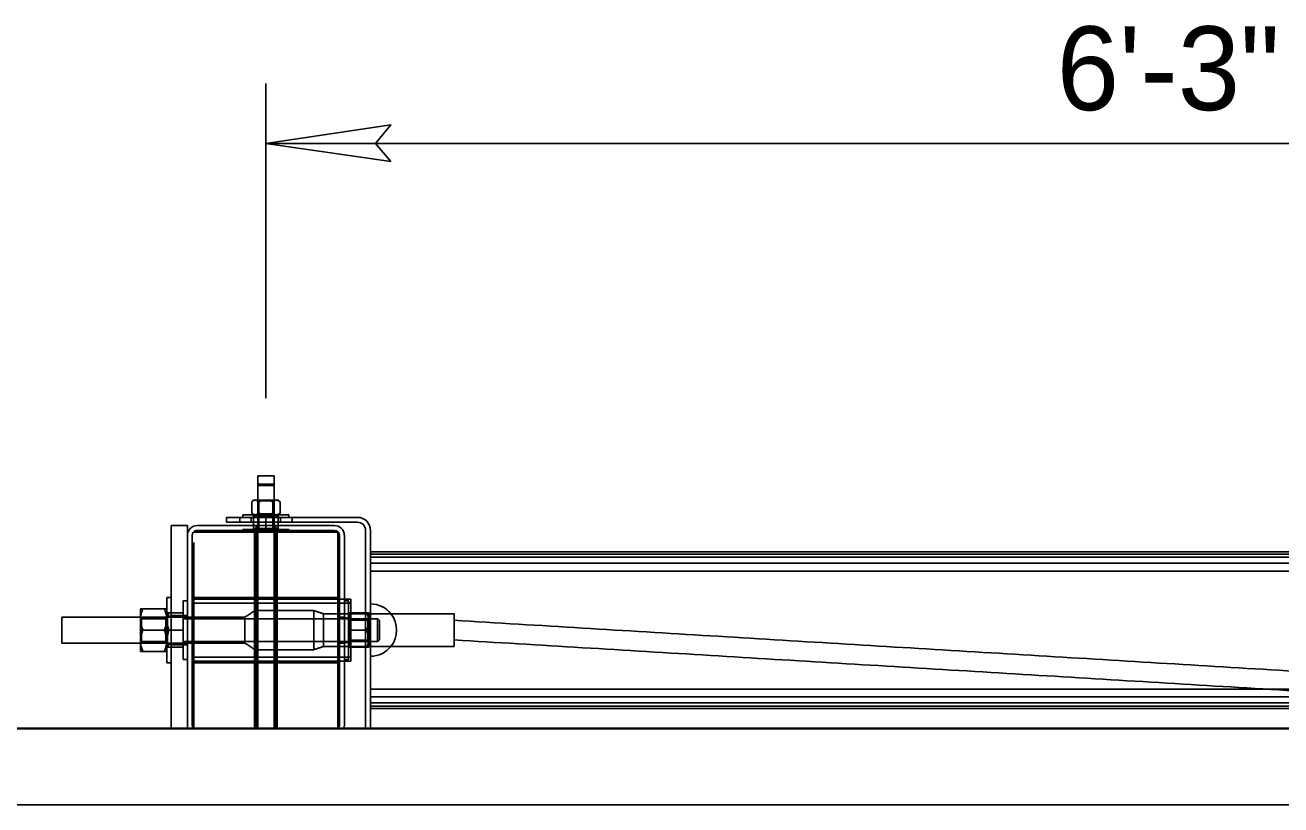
# Model space of a CAD drawing. Extents: x 12.2 to 54.5, y -7.8 to 16.1.
# Drawn here: x 13.517 to 14.416, y 11.987 to 12.545 of the extents above; entities that cross this region are included whole.
import ezdxf

# ---------------------------------------------------------------- set-up
doc = ezdxf.new("R2010")
doc.units = 0
for name, color, linetype in [('BORD-LINE', 7, 'Continuous'), ('DETL-DIMS', 7, 'Continuous'), ('DETL-NOTE', 7, 'Continuous')]:
    doc.layers.add(name, color=color, linetype=linetype)

msp = doc.modelspace()

# ---------------------------------------------------------------- linework, layer by layer
at = {"layer": 'BORD-LINE'}
for p, q in [((13.68348, 12.22238), (13.69519, 12.22238)), ((13.68348, 12.21561), (13.69519, 12.21561)), ((13.68449, 12.21663), (13.69417, 12.21663)), ((13.67919, 12.19579), (13.67919, 12.20392)), ((13.68173, 12.20509), (13.68055, 12.20509)), ((13.68348, 12.20509), (13.68173, 12.20509)), ((13.68933, 12.20509), (13.68348, 12.20509)), ((13.68426, 12.19579), (13.68426, 12.20392)), ((13.68436, 12.20447), (13.69431, 12.20447)), ((13.69519, 12.20509), (13.68933, 12.20509)), ((13.69441, 12.19579), (13.69441, 12.20392)), ((13.69694, 12.20509), (13.69519, 12.20509)), ((13.69812, 12.20509), (13.69694, 12.20509)), ((13.69948, 12.19579), (13.69948, 12.20392)), ((13.68055, 12.19274), (13.66124, 12.19274)), ((13.66124, 12.19274), (13.66124, 12.18923)), ((13.68348, 12.19462), (13.67294, 12.19462)), ((13.6788, 12.19274), (13.6788, 12.18923)), ((13.68494, 12.19455), (13.68055, 12.19455)), ((13.68055, 12.18525), (13.68055, 12.19338)), ((13.69812, 12.19274), (13.68055, 12.19274)), ((13.69519, 12.19464), (13.68348, 12.19464)), ((13.69519, 12.19462), (13.68348, 12.19462)), ((13.68933, 12.19525), (13.68436, 12.19525)), ((13.68436, 12.19394), (13.69431, 12.19394)), ((13.69373, 12.19455), (13.68494, 12.19455)), ((13.69431, 12.19525), (13.68933, 12.19525)), ((13.68933, 12.18525), (13.68933, 12.19338)), ((13.69812, 12.19455), (13.69373, 12.19455)), ((13.70572, 12.19462), (13.69519, 12.19462)), ((13.69812, 12.18525), (13.69812, 12.19338)), ((13.75489, 12.19274), (13.69812, 12.19274)), ((13.69987, 12.19274), (13.69987, 12.18923)), ((13.63314, 12.18689), (13.62143, 12.18689)), ((13.62143, 12.04185), (13.62143, 12.18689)), ((13.63314, 12.04185), (13.63314, 12.18689)), ((13.64016, 12.18689), (13.68055, 12.18689)), ((13.64016, 12.18338), (13.67294, 12.18338)), ((13.66124, 12.18923), (13.68055, 12.18923)), ((13.70572, 12.18408), (13.67294, 12.18408)), ((13.67294, 12.18338), (13.70572, 12.18338)), ((13.68055, 12.18923), (13.69812, 12.18923)), ((13.68055, 12.18689), (13.69812, 12.18689)), ((13.69519, 12.1841), (13.68348, 12.1841)), ((13.69431, 12.18471), (13.68436, 12.18471)), ((13.69812, 12.18923), (13.75489, 12.18923)), ((13.69812, 12.18689), (13.7385, 12.18689)), ((13.70572, 12.18338), (13.7385, 12.18338)), ((13.76075, 12.18338), (13.76075, 12.12367)), ((13.76426, 12.12367), (13.76426, 12.18338)), ((13.63665, 12.12133), (13.63665, 12.17987)), ((13.63782, 12.18221), (13.74084, 12.18221)), ((13.63782, 12.04172), (13.63782, 12.17483)), ((13.74084, 12.18221), (13.74084, 12.04172)), ((13.74201, 12.17987), (13.74201, 12.13421)), ((13.74553, 12.17987), (13.74553, 12.13421)), ((15.01924, 12.16816), (13.76426, 12.16816)), ((13.76426, 12.1307), (13.76426, 12.16816)), ((15.01924, 12.16632), (13.76426, 12.16632)), ((15.01924, 12.16411), (13.76426, 12.16411)), ((15.01924, 12.15983), (13.76426, 12.15983)), ((15.01924, 12.15429), (13.76426, 12.15429)), ((13.61844, 12.08855), (13.61844, 12.13538)), ((13.63014, 12.13304), (13.63014, 12.11197)), ((13.74201, 12.13421), (13.74201, 12.08972)), ((13.74553, 12.13421), (13.74553, 12.08972)), ((13.74852, 12.09089), (13.74852, 12.13304)), ((13.75021, 12.13421), (13.75021, 12.08972)), ((13.54329, 12.1026), (13.54329, 12.12133)), ((13.59948, 12.12719), (13.59948, 12.11958)), ((13.5995, 12.1026), (13.5995, 12.12133)), ((13.60032, 12.10377), (13.60032, 12.12016)), ((13.60135, 12.12719), (13.61656, 12.12719)), ((13.61762, 12.12016), (13.61762, 12.10377)), ((13.61883, 12.11811), (13.61883, 12.12425)), ((13.63014, 12.12425), (13.61993, 12.12425)), ((13.63665, 12.1026), (13.63665, 12.12133)), ((13.6744, 12.1026), (13.6744, 12.12133)), ((13.68143, 12.09792), (13.68143, 12.12601)), ((13.7306, 12.10026), (13.7306, 12.12367)), ((13.74854, 12.10377), (13.74854, 12.12016)), ((13.75016, 12.12425), (13.76142, 12.12425)), ((13.76075, 12.12367), (13.76075, 12.10026)), ((13.76306, 12.11811), (13.76306, 12.12425)), ((13.76426, 12.10026), (13.76426, 12.12367)), ((13.76939, 12.12016), (13.76939, 12.10377)), ((13.82425, 12.10026), (13.82425, 12.12367)), ((13.59948, 12.11958), (13.59948, 12.10436)), ((13.60135, 12.11197), (13.61656, 12.11197)), ((13.61883, 12.10582), (13.61883, 12.11811)), ((13.63014, 12.11197), (13.61993, 12.11197)), ((13.63014, 12.11197), (13.63014, 12.09089)), ((13.74926, 12.1048), (13.74926, 12.11914)), ((13.75016, 12.11197), (13.76142, 12.11197)), ((13.76234, 12.11914), (13.76234, 12.1048)), ((13.76306, 12.10582), (13.76306, 12.11811)), ((13.77063, 12.11892), (13.77063, 12.10501)), ((13.59948, 12.09675), (13.59948, 12.10436)), ((13.61883, 12.09968), (13.61883, 12.10582)), ((13.63665, 12.04407), (13.63665, 12.1026)), ((13.76306, 12.09968), (13.76306, 12.10582)), ((13.60135, 12.09675), (13.61656, 12.09675)), ((13.63014, 12.09968), (13.61993, 12.09968)), ((13.75016, 12.09968), (13.76142, 12.09968)), ((13.76075, 12.10026), (13.76075, 12.04185)), ((13.76426, 12.04185), (13.76426, 12.10026)), ((13.76426, 12.05577), (13.76426, 12.09323)), ((13.74201, 12.08972), (13.74201, 12.04407)), ((13.74553, 12.08972), (13.74553, 12.04407)), ((15.01924, 12.06964), (13.76426, 12.06964)), ((15.01924, 12.0641), (13.76426, 12.0641)), ((15.01924, 12.05983), (13.76426, 12.05983)), ((15.01924, 12.05761), (13.76426, 12.05761)), ((14.55799, 12.05577), (13.76426, 12.05577)), ((13.63782, 12.04185), (12.85346, 12.04185)), ((16.74348, 12.04118), (12.85346, 12.0414)), ((13.74084, 12.04185), (13.63782, 12.04185)), ((13.74084, 12.04172), (13.63782, 12.04172)), ((15.04266, 12.04185), (13.74084, 12.04185)), ((14.85769, 12.04172), (13.74084, 12.04172)), ((16.73075, 11.98677), (12.76364, 11.98677))]:
    msp.add_line(p, q, dxfattribs=at)
for points in [[(13.6335, 12.04185), (13.63328, 12.0427), (13.63314, 12.04407)], [(13.74553, 12.04407), (13.74539, 12.0427), (13.74517, 12.04185)]]:
    msp.add_lwpolyline(points, dxfattribs=at)
for centre, radius, start, end in [((13.75489, 12.18338), 0.00937, 0.0035, 89.99686), ((13.64016, 12.17987), 0.00702, 89.995, 180.00319), ((13.64016, 12.17987), 0.00351, 89.98517, 180.01299), ((13.7385, 12.17987), 0.00702, 359.99681, 90.005), ((13.7385, 12.17987), 0.00351, 0.00659, 89.99525), ((13.75489, 12.18338), 0.00585, 0.0027, 89.99679), ((13.76426, 12.11197), 0.01873, 38.68364, 89.99845), ((13.76426, 12.11197), 0.01873, 321.3166, 38.6834), ((13.76426, 12.11197), 0.01873, 270.00156, 321.31631), ((13.64016, 12.04407), 0.00351, 179.99758, 219.01778), ((13.7385, 12.04407), 0.00351, 320.98222, 0.00242)]:
    msp.add_arc(centre, radius, start, end, dxfattribs=at)
for points, degree in [([(13.68348, 12.19455), (13.68348, 12.22238)], 1), ([(13.69519, 12.22238), (13.69519, 12.19455)], 1), ([(13.68348, 12.21561), (13.68449, 12.21663)], 1), ([(13.69417, 12.21663), (13.69519, 12.21561)], 1), ([(13.67919, 12.20392), (13.68055, 12.20509)], 1), ([(13.67919, 12.20392), (13.67957, 12.20422), (13.6803, 12.2048), (13.68125, 12.20509), (13.68171, 12.20509), (13.68173, 12.20509)], 3), ([(13.68173, 12.20509), (13.68157, 12.20506)], 1), ([(13.68173, 12.20509), (13.68209, 12.20505), (13.68273, 12.20498), (13.68325, 12.20462), (13.68348, 12.20447)], 3), ([(13.68436, 12.20447), (13.68348, 12.20509)], 1), ([(13.68348, 12.20447), (13.6836, 12.2044), (13.68389, 12.20425), (13.68413, 12.20404), (13.68426, 12.20392)], 3), ([(13.68426, 12.20392), (13.68469, 12.20409), (13.68571, 12.2045), (13.6874, 12.20498), (13.68868, 12.20505), (13.68933, 12.20509)], 3), ([(13.68436, 12.19525), (13.68436, 12.20447)], 1), ([(13.68933, 12.20509), (13.68945, 12.20509), (13.69021, 12.20508), (13.69163, 12.20489), (13.6932, 12.20442), (13.69411, 12.20404), (13.69441, 12.20392)], 3), ([(13.69519, 12.20509), (13.69431, 12.20447)], 1), ([(13.69431, 12.20447), (13.69431, 12.19525)], 1), ([(13.69441, 12.20392), (13.69519, 12.20446)], 1), ([(13.69519, 12.20446), (13.69532, 12.20456), (13.69582, 12.20493), (13.69647, 12.20509), (13.69693, 12.20509), (13.69694, 12.20509)], 3), ([(13.69694, 12.20509), (13.6973, 12.20504), (13.69807, 12.20494), (13.69889, 12.2044), (13.69934, 12.20403), (13.69948, 12.20392)], 3), ([(13.69812, 12.20509), (13.69948, 12.20392)], 1), ([(13.6706, 12.18923), (13.6706, 12.19274)], 1), ([(13.67294, 12.19274), (13.67294, 12.19462)], 1), ([(13.68055, 12.19462), (13.67919, 12.19579)], 1), ([(13.67919, 12.19579), (13.67957, 12.19548), (13.6803, 12.1949), (13.68125, 12.19462), (13.68171, 12.19462), (13.68173, 12.19462)], 3), ([(13.68055, 12.19338), (13.68123, 12.19369), (13.6826, 12.19431), (13.68414, 12.19455), (13.68492, 12.19455), (13.68494, 12.19455)], 3), ([(13.68055, 12.19338), (13.68055, 12.19355), (13.68055, 12.19388), (13.68055, 12.19427), (13.68055, 12.19449), (13.68055, 12.19455)], 3), ([(13.68173, 12.19462), (13.68157, 12.19465)], 1), ([(13.68173, 12.19462), (13.68209, 12.19466), (13.68273, 12.19473), (13.68325, 12.19509), (13.68348, 12.19524)], 3), ([(13.68319, 12.19274), (13.68319, 12.19462)], 1), ([(13.68348, 12.19524), (13.6836, 12.19531), (13.68389, 12.19546), (13.68413, 12.19567), (13.68426, 12.19579)], 3), ([(13.68348, 12.19464), (13.68436, 12.19525)], 1), ([(13.68436, 12.19394), (13.68348, 12.19455)], 1), ([(13.68348, 12.04138), (13.68348, 12.19455)], 1), ([(13.68426, 12.19579), (13.68469, 12.19561), (13.68571, 12.1952), (13.6874, 12.19473), (13.68868, 12.19465), (13.68933, 12.19462)], 3), ([(13.68436, 12.18471), (13.68436, 12.19394)], 1), ([(13.68494, 12.19455), (13.68556, 12.19451), (13.68682, 12.19441), (13.68827, 12.19389), (13.68909, 12.1935), (13.68933, 12.19338)], 3), ([(13.68933, 12.19462), (13.68945, 12.19462), (13.69021, 12.19463), (13.69163, 12.19482), (13.6932, 12.19529), (13.69411, 12.19566), (13.69441, 12.19579)], 3), ([(13.68933, 12.19338), (13.69001, 12.19369), (13.69139, 12.19431), (13.69293, 12.19455), (13.69371, 12.19455), (13.69373, 12.19455)], 3), ([(13.69373, 12.19455), (13.69434, 12.19451), (13.6956, 12.19441), (13.69706, 12.19389), (13.69788, 12.1935), (13.69812, 12.19338)], 3), ([(13.69431, 12.19525), (13.69519, 12.19464)], 1), ([(13.69519, 12.19455), (13.69431, 12.19394)], 1), ([(13.69431, 12.19394), (13.69431, 12.18471)], 1), ([(13.69441, 12.19579), (13.69519, 12.19525)], 1), ([(13.69519, 12.19525), (13.69532, 12.19515), (13.69582, 12.19478), (13.69647, 12.19462), (13.69693, 12.19462), (13.69694, 12.19462)], 3), ([(13.69519, 12.19455), (13.69519, 12.04138)], 1), ([(13.69548, 12.19462), (13.69548, 12.19274)], 1), ([(13.69694, 12.19462), (13.6973, 12.19467), (13.69807, 12.19477), (13.69889, 12.1953), (13.69934, 12.19567), (13.69948, 12.19579)], 3), ([(13.69948, 12.19579), (13.69812, 12.19462)], 1), ([(13.69812, 12.19338), (13.69812, 12.19355), (13.69812, 12.19388), (13.69812, 12.19427), (13.69812, 12.19449), (13.69812, 12.19455)], 3), ([(13.70572, 12.19462), (13.70572, 12.19274)], 1), ([(13.70806, 12.19274), (13.70806, 12.18923)], 1), ([(13.67294, 12.18221), (13.67294, 12.18408)], 1), ([(13.68055, 12.18525), (13.68123, 12.18494), (13.6826, 12.18432), (13.68414, 12.18408), (13.68492, 12.18408), (13.68494, 12.18408)], 3), ([(13.68055, 12.18525), (13.68055, 12.18508), (13.68055, 12.18475), (13.68055, 12.18436), (13.68055, 12.18414), (13.68055, 12.18408)], 3), ([(13.68231, 12.18338), (13.68231, 12.18689)], 1), ([(13.68319, 12.18221), (13.68319, 12.18408)], 1), ([(13.68348, 12.1841), (13.68436, 12.18471)], 1), ([(13.68348, 12.18408), (13.68348, 12.1841)], 1), ([(13.68494, 12.18408), (13.68556, 12.18413), (13.68682, 12.18422), (13.68827, 12.18474), (13.68909, 12.18514), (13.68933, 12.18525)], 3), ([(13.68933, 12.18525), (13.69001, 12.18494), (13.69139, 12.18432), (13.69293, 12.18408), (13.69371, 12.18408), (13.69373, 12.18408)], 3), ([(13.69373, 12.18408), (13.69434, 12.18413), (13.6956, 12.18422), (13.69706, 12.18475), (13.69788, 12.18514), (13.69812, 12.18525)], 3), ([(13.69431, 12.18471), (13.69519, 12.1841)], 1), ([(13.69519, 12.1841), (13.69519, 12.18408)], 1), ([(13.69548, 12.18408), (13.69548, 12.18221)], 1), ([(13.69636, 12.18689), (13.69636, 12.18338)], 1), ([(13.69812, 12.18525), (13.69812, 12.18508), (13.69812, 12.18475), (13.69812, 12.18436), (13.69812, 12.18414), (13.69812, 12.18408)], 3), ([(13.70572, 12.18408), (13.70572, 12.18221)], 1), ([(13.68114, 12.04172), (13.68114, 12.18221)], 1), ([(13.68231, 12.04172), (13.68231, 12.18221)], 1), ([(13.69636, 12.18221), (13.69636, 12.04172)], 1), ([(13.69753, 12.18221), (13.69753, 12.04172)], 1), ([(13.61844, 12.13538), (13.62143, 12.13538)], 1), ([(13.63014, 12.13304), (13.63314, 12.13304)], 1), ([(13.63782, 12.13538), (13.74084, 12.13538)], 1), ([(13.63782, 12.13421), (13.74084, 12.13421)], 1), ([(13.63782, 12.13132), (13.75021, 12.13132)], 1), ([(13.74084, 12.13421), (13.75021, 12.13421)], 1), ([(13.74553, 12.13304), (13.74852, 12.13304)], 1), ([(13.54329, 12.12133), (13.59948, 12.12133)], 1), ([(13.60135, 12.12719), (13.60091, 12.12612), (13.60001, 12.12398), (13.59952, 12.12137), (13.59949, 12.11989), (13.59948, 12.11958)], 3), ([(13.59948, 12.12719), (13.59949, 12.12719), (13.59968, 12.12719), (13.60022, 12.12719), (13.60084, 12.12719), (13.60127, 12.12719), (13.60135, 12.12719)], 3), ([(13.59948, 12.12133), (13.63314, 12.12133)], 1), ([(13.59948, 12.12133), (13.5995, 12.12133)], 1), ([(13.5995, 12.12133), (13.60032, 12.12016)], 1), ([(13.60032, 12.12016), (13.61762, 12.12016)], 1), ([(13.61656, 12.12719), (13.61701, 12.12612), (13.6179, 12.12398), (13.6184, 12.12137), (13.61843, 12.11989), (13.61844, 12.11958)], 3), ([(13.61844, 12.12719), (13.61842, 12.12719), (13.61824, 12.12719), (13.61769, 12.12719), (13.61708, 12.12719), (13.61664, 12.12719), (13.61656, 12.12719)], 3), ([(13.61762, 12.12016), (13.61844, 12.12133)], 1), ([(13.61844, 12.12191), (13.62143, 12.12191)], 1), ([(13.61993, 12.12425), (13.61962, 12.12326), (13.619, 12.12125), (13.61889, 12.11916), (13.61883, 12.11811)], 3), ([(13.61883, 12.12425), (13.61889, 12.12425), (13.61912, 12.12425), (13.61949, 12.12425), (13.61979, 12.12425), (13.61993, 12.12425)], 3), ([(13.62143, 12.1225), (13.63314, 12.1225)], 1), ([(13.63014, 12.12075), (13.63314, 12.12075)], 1), ([(13.63014, 12.12016), (13.76939, 12.12016)], 1), ([(13.63314, 12.12133), (13.63782, 12.12133)], 1), ([(13.63782, 12.12133), (13.6744, 12.12133)], 1), ([(13.6744, 12.12133), (13.67532, 12.12188), (13.67705, 12.1229), (13.67937, 12.12451), (13.68078, 12.12554), (13.68143, 12.12601)], 3), ([(13.68143, 12.12601), (13.72357, 12.12601)], 1), ([(13.72357, 12.09792), (13.72357, 12.09801), (13.72357, 12.09836), (13.72357, 12.09915), (13.72357, 12.10043), (13.72357, 12.10216), (13.72357, 12.10426), (13.72357, 12.10666), (13.72357, 12.10926), (13.72357, 12.11197), (13.72357, 12.11467), (13.72357, 12.11727), (13.72357, 12.11967), (13.72357, 12.12177), (13.72357, 12.1235), (13.72357, 12.12478), (13.72357, 12.12557), (13.72357, 12.12592), (13.72357, 12.12601)], 3), ([(13.72357, 12.12601), (13.7306, 12.12367)], 1), ([(13.7306, 12.12367), (13.75021, 12.12367)], 1), ([(13.74201, 12.12133), (13.74553, 12.12133)], 1), ([(13.74553, 12.12075), (13.74852, 12.12075)], 1), ([(13.75016, 12.12425), (13.74973, 12.1233), (13.74886, 12.12138), (13.74853, 12.11923), (13.74852, 12.11814), (13.74852, 12.11811)], 3), ([(13.75016, 12.12425), (13.74993, 12.12425), (13.74947, 12.12425), (13.74892, 12.12425), (13.74861, 12.12425), (13.74852, 12.12425)], 3), ([(13.74852, 12.12016), (13.74854, 12.12016)], 1), ([(13.74854, 12.12016), (13.74926, 12.11914)], 1), ([(13.75021, 12.12367), (13.82425, 12.12367)], 1), ([(13.76142, 12.12425), (13.76185, 12.1233), (13.76272, 12.12138), (13.76306, 12.11923), (13.76306, 12.11814), (13.76306, 12.11811)], 3), ([(13.76142, 12.12425), (13.76165, 12.12425), (13.76212, 12.12425), (13.76266, 12.12425), (13.76297, 12.12425), (13.76306, 12.12425)], 3), ([(13.76234, 12.11914), (13.76306, 12.12016)], 1), ([(13.76939, 12.12016), (13.77063, 12.11892)], 1), ([(13.59948, 12.11958), (13.59954, 12.11858), (13.59967, 12.11656), (13.60046, 12.11403), (13.60111, 12.11253), (13.60135, 12.11197)], 3), ([(13.60135, 12.11197), (13.60091, 12.1109), (13.60001, 12.10876), (13.59952, 12.10615), (13.59949, 12.10467), (13.59948, 12.10436)], 3), ([(13.61844, 12.11958), (13.61837, 12.11858), (13.61825, 12.11656), (13.61746, 12.11403), (13.61681, 12.11253), (13.61656, 12.11197)], 3), ([(13.61656, 12.11197), (13.61701, 12.1109), (13.6179, 12.10876), (13.6184, 12.10615), (13.61843, 12.10467), (13.61844, 12.10436)], 3), ([(13.61883, 12.11811), (13.61883, 12.11796), (13.61884, 12.11686), (13.61908, 12.11477), (13.61964, 12.11291), (13.61993, 12.11197)], 3), ([(13.61993, 12.11197), (13.61962, 12.11097), (13.619, 12.10897), (13.61889, 12.10687), (13.61883, 12.10582)], 3), ([(13.74852, 12.11811), (13.74859, 12.11725), (13.74872, 12.11549), (13.74945, 12.11345), (13.75, 12.1123), (13.75016, 12.11197)], 3), ([(13.75016, 12.11197), (13.74973, 12.11101), (13.74886, 12.10909), (13.74853, 12.10694), (13.74852, 12.10585), (13.74852, 12.10582)], 3), ([(13.74926, 12.11914), (13.76234, 12.11914)], 1), ([(13.76306, 12.11811), (13.763, 12.11725), (13.76287, 12.11549), (13.76213, 12.11345), (13.76158, 12.1123), (13.76142, 12.11197)], 3), ([(13.76142, 12.11197), (13.76185, 12.11101), (13.76272, 12.10909), (13.76306, 12.10694), (13.76306, 12.10585), (13.76306, 12.10582)], 3), ([(13.82425, 12.11899), (14.55799, 12.0745)], 1), ([(13.59948, 12.1026), (13.54329, 12.1026)], 1), ([(13.59948, 12.10436), (13.59954, 12.10336), (13.59967, 12.10134), (13.60046, 12.09881), (13.60111, 12.09731), (13.60135, 12.09675)], 3), ([(13.63314, 12.1026), (13.59948, 12.1026)], 1), ([(13.5995, 12.1026), (13.59948, 12.1026)], 1), ([(13.60032, 12.10377), (13.5995, 12.1026)], 1), ([(13.61762, 12.10377), (13.60032, 12.10377)], 1), ([(13.61844, 12.10436), (13.61837, 12.10336), (13.61825, 12.10134), (13.61746, 12.09881), (13.61681, 12.09731), (13.61656, 12.09675)], 3), ([(13.61844, 12.1026), (13.61762, 12.10377)], 1), ([(13.61883, 12.10582), (13.61883, 12.10568), (13.61884, 12.10457), (13.61908, 12.10248), (13.61964, 12.10062), (13.61993, 12.09968)], 3), ([(13.76939, 12.10377), (13.63014, 12.10377)], 1), ([(13.63314, 12.10318), (13.63014, 12.10318)], 1), ([(13.63782, 12.1026), (13.63314, 12.1026)], 1), ([(13.6744, 12.1026), (13.63782, 12.1026)], 1), ([(13.68143, 12.09792), (13.68078, 12.09839), (13.67937, 12.09942), (13.67705, 12.10103), (13.67532, 12.10206), (13.6744, 12.1026)], 3), ([(13.74553, 12.1026), (13.74201, 12.1026)], 1), ([(13.74852, 12.10318), (13.74553, 12.10318)], 1), ([(13.74852, 12.10582), (13.74859, 12.10496), (13.74872, 12.1032), (13.74945, 12.10117), (13.75, 12.10002), (13.75016, 12.09968)], 3), ([(13.74854, 12.10377), (13.74852, 12.10377)], 1), ([(13.74926, 12.1048), (13.74854, 12.10377)], 1), ([(13.76234, 12.1048), (13.74926, 12.1048)], 1), ([(13.76306, 12.10582), (13.763, 12.10496), (13.76287, 12.1032), (13.76213, 12.10117), (13.76158, 12.10002), (13.76142, 12.09968)], 3), ([(13.76306, 12.10377), (13.76234, 12.1048)], 1), ([(13.77063, 12.10501), (13.76939, 12.10377)], 1), ([(14.55799, 12.06046), (13.82425, 12.10494)], 1), ([(13.59948, 12.09675), (13.59949, 12.09675), (13.59968, 12.09675), (13.60022, 12.09675), (13.60084, 12.09675), (13.60127, 12.09675), (13.60135, 12.09675)], 3), ([(13.61844, 12.09675), (13.61842, 12.09675), (13.61824, 12.09675), (13.61769, 12.09675), (13.61708, 12.09675), (13.61664, 12.09675), (13.61656, 12.09675)], 3), ([(13.62143, 12.10202), (13.61844, 12.10202)], 1), ([(13.61993, 12.09968), (13.61979, 12.09968), (13.61949, 12.09968), (13.61913, 12.09968), (13.61889, 12.09968), (13.61883, 12.09968)], 3), ([(13.63314, 12.10143), (13.62143, 12.10143)], 1), ([(13.72357, 12.09792), (13.68143, 12.09792)], 1), ([(13.7306, 12.10026), (13.72357, 12.09792)], 1), ([(13.75021, 12.10026), (13.7306, 12.10026)], 1), ([(13.75016, 12.09968), (13.74993, 12.09968), (13.74947, 12.09968), (13.74892, 12.09968), (13.74861, 12.09968), (13.74852, 12.09968)], 3), ([(13.82425, 12.10026), (13.75021, 12.10026)], 1), ([(13.76142, 12.09968), (13.76165, 12.09968), (13.76212, 12.09968), (13.76266, 12.09968), (13.76297, 12.09968), (13.76306, 12.09968)], 3), ([(13.62143, 12.08855), (13.61844, 12.08855)], 1), ([(13.63314, 12.09089), (13.63014, 12.09089)], 1), ([(13.75021, 12.09261), (13.63782, 12.09261)], 1), ([(13.74084, 12.08972), (13.63782, 12.08972)], 1), ([(13.74084, 12.08855), (13.63782, 12.08855)], 1), ([(13.75021, 12.08972), (13.74084, 12.08972)], 1), ([(13.74852, 12.09089), (13.74553, 12.09089)], 1)]:
    msp.add_open_spline(points, degree=degree, dxfattribs=at)
at = {"layer": 'DETL-DIMS'}
for p, q in [((13.68933, 12.50357), (13.68933, 12.27816)), ((13.77893, 12.4738), (13.68933, 12.4606)), ((13.77893, 12.4738), (13.76783, 12.4606)), ((15.09417, 12.4606), (13.68933, 12.4606)), ((13.77893, 12.4477), (13.68933, 12.4606)), ((13.77893, 12.4477), (13.76783, 12.4606))]:
    msp.add_line(p, q, dxfattribs=at)
msp.add_lwpolyline([(13.77893, 12.4477), (13.68933, 12.4606), (13.77893, 12.4738), (13.76783, 12.4606)], close=True, dxfattribs=at)

# ---------------------------------------------------------------- texts
at = {"layer": 'DETL-NOTE'}
msp.add_text('6\'-3"', height=0.06, dxfattribs=at).set_placement((14.2556, 12.48446))

doc.saveas('drawing.dxf')
